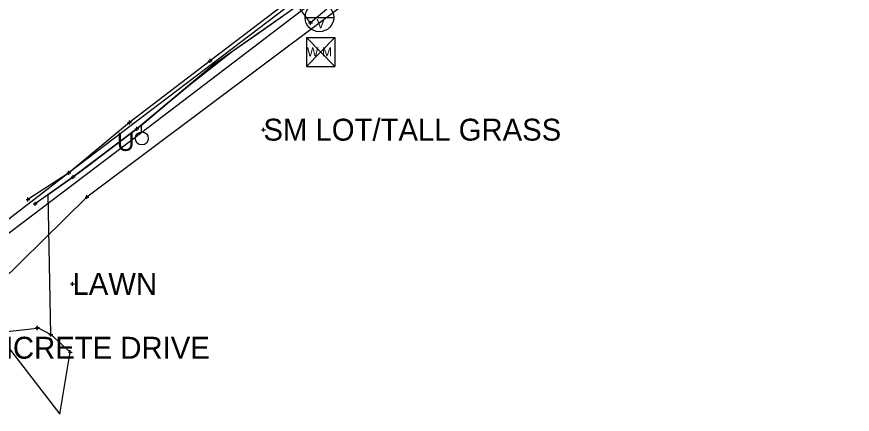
# Model space of a CAD drawing. Extents: x -1 to 1157254, y -1 to 2021979.
# Drawn here: x 1148159 to 1148433.7, y 2017846.7 to 2017977.3 of the extents above; entities that cross this region are included whole.
import ezdxf

# ---------------------------------------------------------------- set-up
doc = ezdxf.new("R2010")
doc.units = 0
for name, color, linetype in [('S_BUILDING_ANNOT', 7, 'Continuous'), ('S_CAL_CORNER_ANNOT', 7, 'Continuous'), ('S_CATCH_BASIN', 7, 'Continuous'), ('S_CONTOUR_ANNOT', 7, 'Continuous'), ('S_CONTOUR_MAJOR', 7, 'Continuous'), ('S_DRIVEWAY_ANNOT', 7, 'Continuous'), ('S_DROP_INLET', 7, 'Continuous'), ('S_DROP_INLET_ANNOT', 7, 'Continuous'), ('S_FENCE', 7, 'Continuous'), ('S_GAS_PUMP_ISLAND_ANNOT', 7, 'Continuous'), ('S_GATE', 7, 'Continuous')]:
    doc.layers.add(name, color=color, linetype=linetype)

msp = doc.modelspace()

# ---------------------------------------------------------------- linework, layer by layer
at = {"layer": 'S_BUILDING_ANNOT'}
for p, q in [((1148254.92, 2017975.25), (1148256.19, 2017975.26)), ((1148255.56, 2017974.62), (1148255.56, 2017975.89)), ((1148255.56, 2017975.26), (1148255.56, 2017975.26)), ((1148221.96, 2017962.79), (1148223.23, 2017962.79)), ((1148222.59, 2017962.15), (1148222.59, 2017963.43)), ((1148222.59, 2017962.79), (1148222.59, 2017962.79)), ((1148223.11, 2017961.59), (1148224.38, 2017961.59)), ((1148223.74, 2017960.95), (1148223.74, 2017962.22)), ((1148223.74, 2017961.59), (1148223.74, 2017961.59)), ((1148195.4, 2017942.53), (1148196.67, 2017942.53)), ((1148196.03, 2017941.9), (1148196.03, 2017943.17)), ((1148196.03, 2017942.53), (1148196.03, 2017942.53)), ((1148197.84, 2017940.51), (1148199.12, 2017940.51)), ((1148198.48, 2017939.87), (1148198.48, 2017941.15)), ((1148198.48, 2017940.51), (1148198.48, 2017940.51)), ((1148239.44, 2017940.19), (1148240.71, 2017940.2)), ((1148240.08, 2017939.56), (1148240.07, 2017940.83)), ((1148240.08, 2017940.2), (1148240.08, 2017940.2)), ((1148175.41, 2017925.96), (1148176.68, 2017925.97)), ((1148175.47, 2017926.04), (1148176.74, 2017926.05)), ((1148176.05, 2017925.33), (1148176.04, 2017926.6)), ((1148176.04, 2017925.96), (1148176.04, 2017925.96)), ((1148176.11, 2017925.41), (1148176.1, 2017926.68)), ((1148176.11, 2017926.04), (1148176.11, 2017926.04)), ((1148176.89, 2017924.68), (1148178.16, 2017924.68)), ((1148177.53, 2017924.04), (1148177.52, 2017925.31)), ((1148177.52, 2017924.68), (1148177.52, 2017924.68)), ((1148162.66, 2017916.64), (1148162.65, 2017917.92)), ((1148181.42, 2017918.06), (1148182.69, 2017918.07)), ((1148182.05, 2017917.43), (1148182.05, 2017918.7)), ((1148182.05, 2017918.06), (1148182.05, 2017918.06)), ((1148162.02, 2017917.28), (1148163.29, 2017917.28)), ((1148162.66, 2017917.28), (1148162.66, 2017917.28)), ((1148164.38, 2017915.86), (1148165.65, 2017915.86)), ((1148165.02, 2017915.22), (1148165.02, 2017916.49)), ((1148165.02, 2017915.86), (1148165.02, 2017915.86)), ((1148177.31, 2017888.9), (1148177.3, 2017890.18)), ((1148176.67, 2017889.54), (1148177.94, 2017889.54)), ((1148177.3, 2017889.54), (1148177.3, 2017889.54)), ((1148165.08, 2017874.98), (1148166.35, 2017874.98)), ((1148165.19, 2017875.16), (1148166.47, 2017875.16)), ((1148165.71, 2017874.34), (1148165.71, 2017875.61)), ((1148165.71, 2017874.98), (1148165.71, 2017874.98)), ((1148165.83, 2017874.53), (1148165.83, 2017875.8)), ((1148165.83, 2017875.16), (1148165.83, 2017875.16)), ((1148169.54, 2017872.91), (1148170.81, 2017872.91)), ((1148170.18, 2017872.27), (1148170.18, 2017873.54)), ((1148170.18, 2017872.91), (1148170.18, 2017872.91)), ((1148175.95, 2017867.08), (1148177.22, 2017867.09)), ((1148176.59, 2017866.45), (1148176.58, 2017867.72)), ((1148176.58, 2017867.09), (1148176.58, 2017867.09))]:
    msp.add_line(p, q, dxfattribs=at)
at = {"layer": 'S_CAL_CORNER_ANNOT'}
msp.add_line((1148253.75, 2017977.06), (1148263.2, 2017977.06), dxfattribs=at)
msp.add_lwpolyline([(1148912.94, 2018389.54), (1148884.02, 2018371.37), (1148841.26, 2018349), (1148782.55, 2018319.82), (1148727.8, 2018292.18), (1148687.32, 2018271.68), (1148647.96, 2018251.03), (1148473.78, 2018149.56), (1148431.39, 2018121.98), (1148409.2, 2018106.42), (1148303.97, 2018024.03), (1148255.75, 2017987.09), (1148260.87, 2017979.68), (1148255.56, 2017975.26), (1148250.28, 2017982.33), (1148176.11, 2017926.04), (1148136.14, 2017895.28)], dxfattribs=at)
msp.add_circle((1148258.48, 2017977.07), 4.71, dxfattribs=at)
at = {"layer": 'S_CATCH_BASIN'}
msp.add_line((1148199.98, 2017939.46), (1148199.98, 2017941.56), dxfattribs=at)
msp.add_circle((1148200.1, 2017937.32), 2.13, dxfattribs=at)
at = {"layer": 'S_CONTOUR_ANNOT'}
for p, q in [((1148254.19, 2017970.49), (1148263.53, 2017970.49)), ((1148254.19, 2017970.49), (1148254.19, 2017961)), ((1148254.19, 2017970.49), (1148263.53, 2017961)), ((1148263.53, 2017970.49), (1148254.19, 2017961)), ((1148263.53, 2017970.49), (1148263.53, 2017961)), ((1148254.19, 2017961), (1148263.53, 2017961))]:
    msp.add_line(p, q, dxfattribs=at)
at = {"layer": 'S_DRIVEWAY_ANNOT'}
for points in [[(1148431.21, 2018122.21), (1148409.57, 2018105.71), (1148389.94, 2018091.01), (1148358.15, 2018067.12), (1148319.85, 2018037.3), (1148284.61, 2018010.47), (1148252.3, 2017985.46), (1148222.59, 2017962.79), (1148196.03, 2017942.53), (1148176.04, 2017925.96), (1148162.66, 2017917.28)], [(1148432.34, 2018120.62), (1148410.15, 2018104.35), (1148390.95, 2018090.03), (1148359.43, 2018065.73), (1148320.43, 2018035.94), (1148286.46, 2018009.58), (1148254.49, 2017983.21), (1148223.74, 2017961.59), (1148198.48, 2017940.51), (1148177.52, 2017924.68), (1148165.02, 2017915.86)], [(1148165.83, 2017875.16), (1148170.18, 2017872.91), (1148176.58, 2017867.09)]]:
    msp.add_lwpolyline(points, dxfattribs=at)
at = {"layer": 'S_DROP_INLET'}
msp.add_lwpolyline([(1149478.88, 2018922.64), (1149385.84, 2018831.36), (1149330.57, 2018775.16), (1149250.6, 2018696.8), (1149231.5, 2018678.75), (1149169.67, 2018614.3), (1149128.45, 2018577.04), (1149075.89, 2018529.44), (1149016.28, 2018476.33), (1148941.34, 2018408.7), (1148861.11, 2018354.7), (1148778.49, 2018311.96), (1148755.86, 2018297.95), (1148577.39, 2018201.52), (1148460.64, 2018136.54), (1148334.57, 2018041.74), (1148195.53, 2017935.77), (1148138.82, 2017892.99)], dxfattribs=at)
at = {"layer": 'S_DROP_INLET_ANNOT'}
msp.add_lwpolyline([(1148105.09, 2017868.3), (1148165.71, 2017874.98)], dxfattribs=at)
at = {"layer": 'S_FENCE'}
msp.add_lwpolyline([(1149562.21, 2019005.4), (1149486.21, 2018927.15), (1149466.96, 2018916.4), (1149448.15, 2018887.45), (1149385.38, 2018826.9), (1149357.5, 2018803.66), (1149334.17, 2018772.97), (1149278.68, 2018714.02), (1149266.21, 2018707.99), (1149250.6, 2018696.75), (1149241.46, 2018677.2), (1149179.13, 2018611.74), (1149130.37, 2018567.15), (1149080.16, 2018520.92), (1149020.19, 2018471.53), (1148946.08, 2018397.31), (1148842.28, 2018340.54), (1148783.26, 2018310.71), (1148755.06, 2018299.13), (1148580.09, 2018196.31), (1148464.77, 2018128.06), (1148357.29, 2018049.22), (1148182.05, 2017918.06), (1148146.03, 2017882.74)], dxfattribs=at)
at = {"layer": 'S_GAS_PUMP_ISLAND_ANNOT'}
msp.add_lwpolyline([(1148155.09, 2017870.18), (1148173.15, 2017846.7), (1148176.58, 2017867.09), (1148170.18, 2017872.91), (1148169.36, 2017918.92), (1148177.52, 2017924.68), (1148182.52, 2017928.45), (1148190.5, 2017934.48), (1148198.48, 2017940.51), (1148200.71, 2017942.37), (1148208.39, 2017948.77), (1148216.07, 2017955.18), (1148229.95, 2017965.95), (1148238.13, 2017971.71), (1148246.31, 2017977.46)], dxfattribs=at)

# ---------------------------------------------------------------- texts
at = {"layer": 'S_CAL_CORNER_ANNOT'}
msp.add_text('V', height=3, dxfattribs=at).set_placement((1148257.56, 2017973.54))
at = {"layer": 'S_CONTOUR_ANNOT'}
msp.add_text('W M', height=2.999, dxfattribs=at).set_placement((1148254.4, 2017964.26))
at = {"layer": 'S_CONTOUR_MAJOR'}
msp.add_text('U', height=6, dxfattribs=at).set_placement((1148191.9, 2017933.22))
at = {"layer": 'S_GATE'}
for s, p in [('SM LOT/TALL GRASS', (1148240.08, 2017936.6)), ('LAWN', (1148177.3, 2017885.94)), ('CONCRETE DRIVE', (1148136.33, 2017864.96))]:
    msp.add_text(s, height=7.2, dxfattribs=at).set_placement(p)

doc.saveas('drawing.dxf')
